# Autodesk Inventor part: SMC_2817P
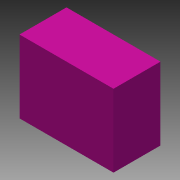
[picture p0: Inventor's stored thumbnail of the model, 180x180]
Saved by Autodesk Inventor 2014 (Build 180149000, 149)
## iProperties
Shininess: 64.0
Length Units: 11272
Angle Units: 11279
Time Units: 11290
Mass Units: 11286
Length Display Precision: 3
Angle Display Precision: 2
Compacted: True
Part Number: SMC_2817P
Document SubType Name: Modeling
Created: 2003-04
Designer: t_enrig
Manufacturer: Standard
Standards Organization: Custom
Density: 1 g/cm^3
Mass: 0.0674164 g
Surface Area: 1.03613 cm^2
Volume: 0.0674164 cm^3
Material: Generic
Appearance: TranslatedColorStyle
Density: 0.0
Volumn: 0.0
Area: 0.0
PropertySet Name: Model Information
Control State: 0
Master: False
Checked Out: False
Author: t_enrig
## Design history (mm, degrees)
feature "Base1"
body "Solid1"
